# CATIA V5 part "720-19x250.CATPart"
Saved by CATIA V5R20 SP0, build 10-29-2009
Part number: 720-19x250
Definition: NONE
Nomenclature: 720-19x250
Source: Unknown
Description: 720-19x250
Bounding box of the stored display mesh (mm): x 0 to 250, y -9.5 to 9.5, z -9.5 to 9.5
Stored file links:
  C:\Users\Utente\Desktop\IO LAVORO\3D X SITO CF\X SITO\720\720-19x250.CATPart
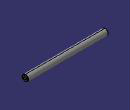
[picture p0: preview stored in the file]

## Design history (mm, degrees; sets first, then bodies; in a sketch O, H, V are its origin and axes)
Body1 "720-19x250" (main body)
  Solid1: solid without history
